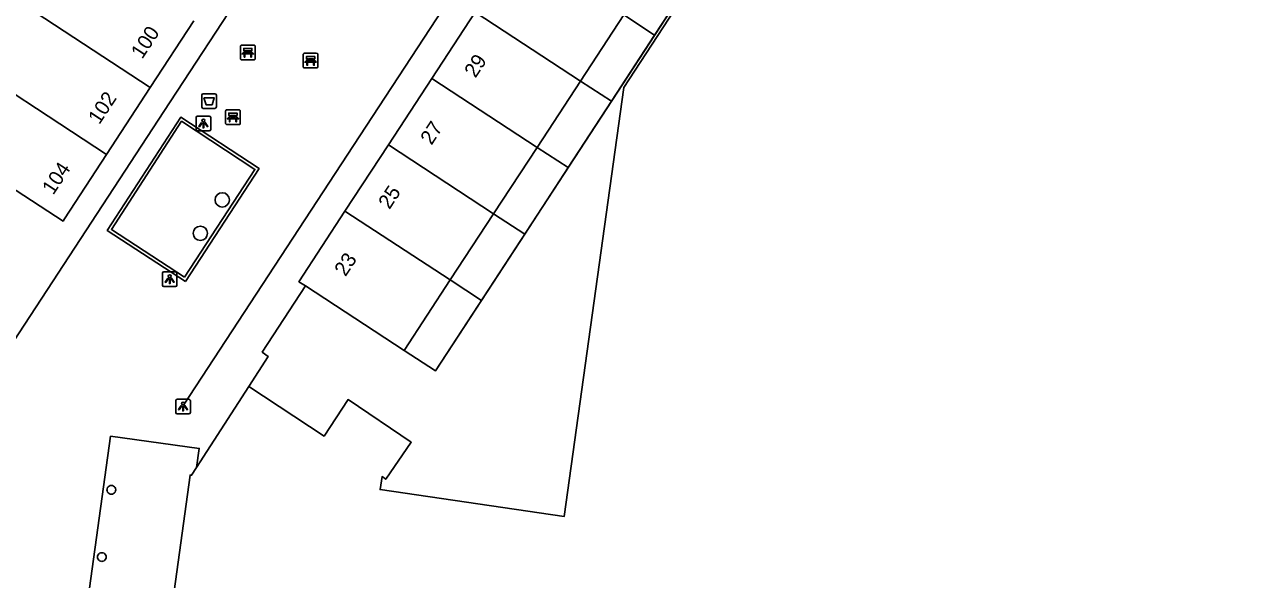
# Model space of a CAD drawing. Extents: x 155640 to 156810, y 382822 to 384046.
# Drawn here: x 156426.7 to 156509.5, y 383692.6 to 383730.5 of the extents above; entities that cross this region are included whole.
import ezdxf

# ---------------------------------------------------------------- set-up
doc = ezdxf.new("R2010")
doc.units = 0
for name, color, linetype in [('IMGEO_Afvalbak', 7, 'Continuous'), ('IMGEO_Bank', 7, 'Continuous'), ('IMGEO_Boom', 7, 'Continuous'), ('IMGEO_Lichtpunt', 7, 'Continuous'), ('IMGEO_Lijnafwatering', 7, 'Continuous'), ('IMGEO_Muur', 7, 'Continuous'), ('IMGEO_Pand', 7, 'Continuous'), ('IMGEO_Pand_nummerreeks', 7, 'Continuous'), ('IMGEO_Pand_overbouw', 7, 'Continuous'), ('IMGEO_Voetpad_open', 7, 'Continuous')]:
    doc.layers.add(name, color=color, linetype=linetype)

msp = doc.modelspace()

# ---------------------------------------------------------------- linework, layer by layer
at = {"layer": 'IMGEO_Afvalbak'}
for p, q in [((156438.818, 383724.836), (156438.818, 383725.636)), ((156438.818, 383725.636), (156438.818, 383724.836)), ((156438.918, 383725.736), (156439.708, 383725.736)), ((156439.708, 383725.736), (156438.918, 383725.736)), ((156439.808, 383725.636), (156439.808, 383724.836)), ((156439.808, 383724.836), (156439.808, 383725.636)), ((156439.708, 383724.736), (156438.918, 383724.736)), ((156438.918, 383724.736), (156439.708, 383724.736))]:
    msp.add_line(p, q, dxfattribs=at)
msp.add_lwpolyline([(156438.961, 383725.45), (156439.665, 383725.45), (156439.516, 383724.98), (156439.11, 383724.98), (156438.961, 383725.45)], dxfattribs=at)
for centre, start, end in [((156438.918, 383725.636), 90, 180), ((156438.918, 383725.636), 90, 180), ((156439.708, 383725.636), 0, 90), ((156439.708, 383725.636), 360, 90), ((156438.918, 383724.836), 180, 270), ((156438.918, 383724.836), 180, 270), ((156439.708, 383724.836), 270, 0), ((156439.708, 383724.836), 270, 0)]:
    msp.add_arc(centre, 0.1, start, end, dxfattribs=at)
at = {"layer": 'IMGEO_Bank'}
for p, q in [((156441.457, 383728.121), (156441.457, 383728.962)), ((156441.457, 383728.962), (156441.457, 383728.121)), ((156441.532, 383729.046), (156442.373, 383729.046)), ((156442.373, 383729.046), (156441.532, 383729.046)), ((156442.457, 383728.971), (156442.457, 383728.13)), ((156442.457, 383728.13), (156442.457, 383728.971)), ((156442.382, 383728.046), (156441.541, 383728.046)), ((156441.541, 383728.046), (156442.382, 383728.046)), ((156442.154, 383728.444), (156441.761, 383728.444)), ((156441.766, 383728.552), (156441.766, 383728.658)), ((156441.81, 383728.658), (156441.81, 383728.552)), ((156442.098, 383728.664), (156441.816, 383728.664)), ((156441.816, 383728.546), (156442.098, 383728.546)), ((156442.104, 383728.552), (156442.104, 383728.658)), ((156442.148, 383728.658), (156442.148, 383728.552)), ((156445.736, 383727.566), (156445.736, 383728.407)), ((156445.736, 383728.407), (156445.736, 383727.566)), ((156445.811, 383728.491), (156446.652, 383728.491)), ((156446.652, 383728.491), (156445.811, 383728.491)), ((156446.045, 383727.997), (156446.045, 383728.103)), ((156446.089, 383728.103), (156446.089, 383727.997)), ((156446.377, 383728.109), (156446.095, 383728.109)), ((156446.095, 383727.991), (156446.377, 383727.991)), ((156446.383, 383727.997), (156446.383, 383728.103)), ((156446.427, 383728.103), (156446.427, 383727.997)), ((156446.736, 383728.416), (156446.736, 383727.575)), ((156446.736, 383727.575), (156446.736, 383728.416)), ((156446.661, 383727.491), (156445.82, 383727.491)), ((156445.82, 383727.491), (156446.661, 383727.491)), ((156446.433, 383727.889), (156446.04, 383727.889)), ((156440.517, 383724.632), (156441.358, 383724.632)), ((156441.358, 383724.632), (156440.517, 383724.632)), ((156440.442, 383723.707), (156440.442, 383724.548)), ((156440.442, 383724.548), (156440.442, 383723.707)), ((156441.139, 383724.03), (156440.746, 383724.03)), ((156440.751, 383724.138), (156440.751, 383724.244)), ((156440.795, 383724.244), (156440.795, 383724.138)), ((156441.083, 383724.25), (156440.801, 383724.25)), ((156440.801, 383724.132), (156441.083, 383724.132)), ((156441.089, 383724.138), (156441.089, 383724.244)), ((156441.133, 383724.244), (156441.133, 383724.138)), ((156441.442, 383724.557), (156441.442, 383723.716)), ((156441.442, 383723.716), (156441.442, 383724.557)), ((156441.367, 383723.632), (156440.526, 383723.632)), ((156440.526, 383723.632), (156441.367, 383723.632))]:
    msp.add_line(p, q, dxfattribs=at)
for points in [[(156441.76, 383728.664), (156441.674, 383728.664), (156441.674, 383728.825), (156442.237, 383728.825), (156442.237, 383728.664), (156442.154, 383728.664)], [(156441.704, 383728.444), (156441.562, 383728.444), (156441.674, 383728.546), (156441.76, 383728.546)], [(156441.754, 383728.437), (156441.754, 383728.23), (156441.711, 383728.23), (156441.711, 383728.437)], [(156442.154, 383728.546), (156442.237, 383728.546), (156442.349, 383728.444), (156442.21, 383728.444)], [(156442.204, 383728.437), (156442.204, 383728.23), (156442.16, 383728.23), (156442.16, 383728.437)], [(156445.983, 383727.889), (156445.841, 383727.889), (156445.953, 383727.991), (156446.039, 383727.991)], [(156446.039, 383728.109), (156445.953, 383728.109), (156445.953, 383728.27), (156446.516, 383728.27), (156446.516, 383728.109), (156446.433, 383728.109)], [(156446.433, 383727.991), (156446.516, 383727.991), (156446.628, 383727.889), (156446.489, 383727.889)], [(156446.033, 383727.882), (156446.033, 383727.675), (156445.99, 383727.675), (156445.99, 383727.882)], [(156446.483, 383727.882), (156446.483, 383727.675), (156446.439, 383727.675), (156446.439, 383727.882)], [(156440.689, 383724.03), (156440.547, 383724.03), (156440.659, 383724.132), (156440.745, 383724.132)], [(156440.745, 383724.25), (156440.659, 383724.25), (156440.659, 383724.411), (156441.222, 383724.411), (156441.222, 383724.25), (156441.139, 383724.25)], [(156440.739, 383724.023), (156440.739, 383723.816), (156440.696, 383723.816), (156440.696, 383724.023)], [(156441.139, 383724.132), (156441.222, 383724.132), (156441.334, 383724.03), (156441.195, 383724.03)], [(156441.189, 383724.023), (156441.189, 383723.816), (156441.145, 383723.816), (156441.145, 383724.023)]]:
    msp.add_lwpolyline(points, dxfattribs=at)
for centre, radius, start, end in [((156441.535, 383728.968), 0.0779, 92.4484, 184.28452), ((156441.535, 383728.968), 0.0779, 92.4484, 184.28452), ((156442.379, 383728.968), 0.0779, 2.4484, 94.28452), ((156442.379, 383728.968), 0.0779, 2.4484, 94.28452), ((156441.535, 383728.124), 0.0779, 182.4484, 274.28452), ((156441.535, 383728.124), 0.0779, 182.4484, 274.28452), ((156441.704, 383728.437), 0.00671, 2.89567, 87.10433), ((156441.761, 383728.437), 0.00671, 92.89567, 177.10433), ((156441.759, 383728.657), 0.00671, 2.89567, 87.10433), ((156441.759, 383728.553), 0.00671, 272.89567, 357.10433), ((156441.816, 383728.657), 0.00671, 92.89567, 177.10433), ((156441.816, 383728.553), 0.00671, 182.89567, 267.10433), ((156442.098, 383728.657), 0.00671, 2.89567, 87.10433), ((156442.098, 383728.553), 0.00671, 272.89567, 357.10433), ((156442.155, 383728.657), 0.00671, 92.89567, 177.10433), ((156442.155, 383728.553), 0.00671, 182.89567, 267.10433), ((156442.153, 383728.437), 0.00671, 2.89567, 87.10433), ((156442.21, 383728.437), 0.00671, 92.89567, 177.10433), ((156442.379, 383728.124), 0.0779, 272.4484, 4.28452), ((156442.379, 383728.124), 0.0779, 272.4484, 4.28452), ((156445.814, 383728.413), 0.0779, 92.4484, 184.28452), ((156445.814, 383728.413), 0.0779, 92.4484, 184.28452), ((156446.038, 383728.102), 0.00671, 2.89567, 87.10433), ((156446.038, 383727.998), 0.00671, 272.89567, 357.10433), ((156446.095, 383728.102), 0.00671, 92.89567, 177.10433), ((156446.095, 383727.998), 0.00671, 182.89567, 267.10433), ((156446.377, 383728.102), 0.00671, 2.89567, 87.10433), ((156446.377, 383727.998), 0.00671, 272.89567, 357.10433), ((156446.434, 383728.102), 0.00671, 92.89567, 177.10433), ((156446.434, 383727.998), 0.00671, 182.89567, 267.10433), ((156446.658, 383728.413), 0.0779, 2.4484, 94.28452), ((156446.658, 383728.413), 0.0779, 2.4484, 94.28452), ((156445.814, 383727.569), 0.0779, 182.4484, 274.28452), ((156445.814, 383727.569), 0.0779, 182.4484, 274.28452), ((156445.983, 383727.882), 0.00671, 2.89567, 87.10433), ((156446.04, 383727.882), 0.00671, 92.89567, 177.10433), ((156446.432, 383727.882), 0.00671, 2.89567, 87.10433), ((156446.489, 383727.882), 0.00671, 92.89567, 177.10433), ((156446.658, 383727.569), 0.0779, 272.4484, 4.28452), ((156446.658, 383727.569), 0.0779, 272.4484, 4.28452), ((156440.52, 383724.554), 0.0779, 92.4484, 184.28452), ((156440.52, 383724.554), 0.0779, 92.4484, 184.28452), ((156441.364, 383724.554), 0.0779, 2.4484, 94.28452), ((156441.364, 383724.554), 0.0779, 2.4484, 94.28452), ((156440.689, 383724.023), 0.00671, 2.89567, 87.10433), ((156440.746, 383724.023), 0.00671, 92.89567, 177.10433), ((156440.744, 383724.243), 0.00671, 2.89567, 87.10433), ((156440.744, 383724.139), 0.00671, 272.89567, 357.10433), ((156440.801, 383724.243), 0.00671, 92.89567, 177.10433), ((156440.801, 383724.139), 0.00671, 182.89567, 267.10433), ((156441.083, 383724.243), 0.00671, 2.89567, 87.10433), ((156441.083, 383724.139), 0.00671, 272.89567, 357.10433), ((156441.14, 383724.243), 0.00671, 92.89567, 177.10433), ((156441.14, 383724.139), 0.00671, 182.89567, 267.10433), ((156441.138, 383724.023), 0.00671, 2.89567, 87.10433), ((156441.195, 383724.023), 0.00671, 92.89567, 177.10433), ((156440.52, 383723.71), 0.0779, 182.4484, 274.28452), ((156440.52, 383723.71), 0.0779, 182.4484, 274.28452), ((156441.364, 383723.71), 0.0779, 272.4484, 4.28452), ((156441.364, 383723.71), 0.0779, 272.4484, 4.28452)]:
    msp.add_arc(centre, radius, start, end, dxfattribs=at)
at = {"layer": 'IMGEO_Boom'}
for centre in [(156440.21, 383718.49), (156438.717, 383716.209)]:
    msp.add_circle(centre, 0.489, dxfattribs=at)
at = {"layer": 'IMGEO_Lichtpunt'}
for p, q in [((156438.425, 383724.102), (156438.425, 383723.295)), ((156438.425, 383724.102), (156438.425, 383723.295)), ((156439.327, 383724.197), (156438.519, 383724.197)), ((156439.327, 383724.197), (156438.519, 383724.197)), ((156439.421, 383723.295), (156439.421, 383724.102)), ((156439.421, 383723.295), (156439.421, 383724.102)), ((156438.519, 383723.201), (156439.327, 383723.201)), ((156438.519, 383723.201), (156439.327, 383723.201)), ((156436.126, 383713.484), (156436.126, 383712.677)), ((156436.126, 383713.484), (156436.126, 383712.677)), ((156437.028, 383713.579), (156436.22, 383713.579)), ((156437.028, 383713.579), (156436.22, 383713.579)), ((156437.122, 383712.677), (156437.122, 383713.484)), ((156437.122, 383712.677), (156437.122, 383713.484)), ((156436.22, 383712.583), (156437.028, 383712.583)), ((156436.22, 383712.583), (156437.028, 383712.583)), ((156437.038, 383704.793), (156437.038, 383703.986)), ((156437.038, 383704.793), (156437.038, 383703.986)), ((156437.94, 383704.888), (156437.132, 383704.888)), ((156437.94, 383704.888), (156437.132, 383704.888)), ((156438.034, 383703.986), (156438.034, 383704.793)), ((156438.034, 383703.986), (156438.034, 383704.793)), ((156437.132, 383703.892), (156437.94, 383703.892)), ((156437.132, 383703.892), (156437.94, 383703.892))]:
    msp.add_line(p, q, dxfattribs=at)
for points in [[(156438.799, 383723.766), (156438.838, 383723.738), (156438.65, 383723.476), (156438.612, 383723.503), (156438.799, 383723.766)], [(156438.901, 383723.718), (156438.948, 383723.718), (156438.948, 383723.396), (156438.901, 383723.396), (156438.901, 383723.718)], [(156439.011, 383723.738), (156439.049, 383723.765), (156439.236, 383723.503), (156439.197, 383723.475), (156439.011, 383723.738)], [(156436.5, 383713.148), (156436.539, 383713.12), (156436.351, 383712.858), (156436.313, 383712.885), (156436.5, 383713.148)], [(156436.602, 383713.1), (156436.649, 383713.1), (156436.649, 383712.778), (156436.602, 383712.778), (156436.602, 383713.1)], [(156436.712, 383713.12), (156436.75, 383713.147), (156436.937, 383712.885), (156436.898, 383712.857), (156436.712, 383713.12)], [(156437.412, 383704.457), (156437.451, 383704.429), (156437.263, 383704.167), (156437.225, 383704.194), (156437.412, 383704.457)], [(156437.514, 383704.409), (156437.561, 383704.409), (156437.561, 383704.087), (156437.514, 383704.087), (156437.514, 383704.409)], [(156437.624, 383704.429), (156437.662, 383704.456), (156437.849, 383704.194), (156437.81, 383704.166), (156437.624, 383704.429)]]:
    msp.add_lwpolyline(points, dxfattribs=at)
for centre in [(156438.924, 383723.9), (156436.625, 383713.282), (156437.537, 383704.591)]:
    msp.add_circle(centre, 0.0994, dxfattribs=at)
for centre, start, end in [((156438.519, 383724.102), 90, 180), ((156438.519, 383724.102), 90, 180), ((156439.327, 383724.102), 0, 90), ((156439.327, 383724.102), 0, 90), ((156438.519, 383723.295), 180, 270), ((156438.519, 383723.295), 180, 270), ((156439.327, 383723.295), 270, 0), ((156439.327, 383723.295), 270, 360), ((156436.22, 383713.484), 90, 180), ((156436.22, 383713.484), 90, 180), ((156437.028, 383713.484), 0, 90), ((156437.028, 383713.484), 0, 90), ((156436.22, 383712.677), 180, 270), ((156436.22, 383712.677), 180, 270), ((156437.028, 383712.677), 270, 0), ((156437.028, 383712.677), 270, 360), ((156437.132, 383704.793), 90, 180), ((156437.132, 383704.793), 90, 180), ((156437.94, 383704.793), 0, 90), ((156437.94, 383704.793), 0, 90), ((156437.132, 383703.986), 180, 270), ((156437.132, 383703.986), 180, 270), ((156437.94, 383703.986), 270, 0), ((156437.94, 383703.986), 270, 360)]:
    msp.add_arc(centre, 0.0946, start, end, dxfattribs=at)
at = {"layer": 'IMGEO_Lijnafwatering'}
for points in [[(156447.726, 383742.098), (156436.226, 383724.532)], [(156459.635, 383738.197), (156449.169, 383722.207)], [(156436.226, 383724.532), (156424.059, 383705.945)], [(156449.169, 383722.207), (156437.575, 383704.494)]]:
    msp.add_lwpolyline(points, dxfattribs=at)
at = {"layer": 'IMGEO_Muur'}
for points in [[(156437.703, 383712.932), (156432.369, 383716.413), (156437.382, 383724.131), (156442.721, 383720.623), (156437.703, 383712.932)], [(156437.645, 383713.209), (156442.445, 383720.565), (156437.44, 383723.854), (156432.646, 383716.471), (156437.645, 383713.209)], [(156442.937, 383708.11), (156445.881, 383712.618)], [(156442.019, 383705.761), (156443.341, 383707.811), (156442.937, 383708.11)]]:
    msp.add_lwpolyline(points, dxfattribs=at)
at = {"layer": 'IMGEO_Pand'}
for points in [[(156504.403, 383768.001), (156526.125, 383742.921), (156525.429, 383738.064), (156524.746, 383738.162), (156523.866, 383731.807), (156524.529, 383731.715), (156519.308, 383694.178), (156518.219, 383694.329), (156517.212, 383687.287), (156518.313, 383687.13), (156516.68, 383675.304), (156436.208, 383686.52), (156438.014, 383699.718), (156438.115, 383699.703), (156438.461, 383700.239)], [(156495.141, 383758.761), (156489.522, 383750.169), (156483.796, 383750.953), (156467.607, 383726.148), (156463.541, 383696.89), (156450.981, 383698.723), (156451.111, 383699.61), (156451.369, 383699.433), (156453.11, 383701.958), (156448.797, 383704.86), (156447.156, 383702.372), (156442.019, 383705.761)], [(156424.193, 383733.426), (156435.302, 383726.149)], [(156454.503, 383726.765), (156457.463, 383731.289)], [(156464.65, 383726.595), (156457.463, 383731.289)], [(156438.283, 383730.707), (156435.302, 383726.149)], [(156464.65, 383726.595), (156467.606, 383731.11)], [(156432.321, 383721.592), (156421.209, 383728.871)], [(156451.542, 383722.239), (156454.503, 383726.765)], [(156461.689, 383722.072), (156454.503, 383726.765)], [(156461.689, 383722.072), (156464.65, 383726.595)], [(156435.302, 383726.149), (156432.321, 383721.592)], [(156448.583, 383717.716), (156451.542, 383722.239)], [(156458.727, 383717.547), (156451.542, 383722.239)], [(156432.321, 383721.592), (156429.451, 383717.202), (156429.348, 383717.045), (156425.619, 383719.482)], [(156458.727, 383717.547), (156461.689, 383722.072)], [(156445.881, 383712.618), (156445.437, 383712.908), (156448.583, 383717.716)], [(156455.766, 383713.025), (156448.583, 383717.716)], [(156455.766, 383713.025), (156458.727, 383717.547)], [(156445.881, 383712.618), (156452.619, 383708.217)], [(156452.619, 383708.217), (156455.766, 383713.025)], [(156438.461, 383700.239), (156442.019, 383705.761)]]:
    msp.add_lwpolyline(points, dxfattribs=at)
for centre, radius, start, end in [((156432.648, 383698.709), 0.3, 120.17726, 239.82274), ((156432.649, 383698.711), 0.298, 359.77259, 120.57324), ((156432.647, 383698.71), 0.3, 240.00001, 0.03673), ((156431.995, 383694.12), 0.3, 119.98184, 240.23852), ((156431.995, 383694.12), 0.3, 359.96327, 119.99999), ((156431.995, 383694.121), 0.3, 240.34254, 359.80469)]:
    msp.add_arc(centre, radius, start, end, dxfattribs=at)
at = {"layer": 'IMGEO_Pand_overbouw'}
for points in [[(156467.606, 383731.11), (156469.71, 383729.736), (156472.662, 383734.259), (156470.565, 383735.629)], [(156467.606, 383731.11), (156464.65, 383726.595), (156466.761, 383725.217), (156469.71, 383729.736)], [(156461.689, 383722.072), (156463.806, 383720.69), (156466.761, 383725.217), (156464.65, 383726.595)], [(156461.689, 383722.072), (156458.727, 383717.547), (156460.85, 383716.161), (156463.806, 383720.69)], [(156455.766, 383713.025), (156457.896, 383711.634), (156460.85, 383716.161), (156458.727, 383717.547)], [(156455.766, 383713.025), (156452.619, 383708.217), (156454.756, 383706.822), (156457.896, 383711.634)]]:
    msp.add_lwpolyline(points, close=True, dxfattribs=at)
msp.add_lwpolyline([(156436.208, 383686.52), (156438.014, 383699.718), (156438.115, 383699.703), (156438.461, 383700.239), (156438.64, 383701.529), (156432.591, 383702.361), (156430.466, 383687.075)], dxfattribs=at)
at = {"layer": 'IMGEO_Voetpad_open'}
for points in [[(156452.619, 383708.217), (156454.756, 383706.822), (156484.681, 383752.675), (156482.61, 383754.028)], [(156442.019, 383705.761), (156443.341, 383707.811), (156442.937, 383708.11), (156445.881, 383712.618)], [(156438.461, 383700.239), (156438.64, 383701.529), (156432.591, 383702.361), (156430.466, 383687.075), (156436.756, 383686.197), (156436.634, 383685.326), (156463.32, 383681.604), (156463.412, 383682.264), (156509.833, 383675.802), (156509.748, 383675.153), (156517.613, 383674.051)]]:
    msp.add_lwpolyline(points, dxfattribs=at)

# ---------------------------------------------------------------- texts
at = {"layer": 'IMGEO_Pand_nummerreeks'}
for s, rotation, p in [('100', 56.61969, (156434.747, 383728.05)), ('29', 56.80304, (156457.484, 383726.755)), ('102', 56.61969, (156431.824, 383723.581)), ('27', 56.80877, (156454.487, 383722.175)), ('104', 56.61969, (156428.681, 383718.775)), ('25', 56.80877, (156451.62, 383717.792)), ('23', 56.80304, (156448.622, 383713.209))]:
    msp.add_text(s, height=1, rotation=rotation, dxfattribs=at).set_placement(p)

doc.saveas('drawing.dxf')
